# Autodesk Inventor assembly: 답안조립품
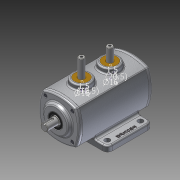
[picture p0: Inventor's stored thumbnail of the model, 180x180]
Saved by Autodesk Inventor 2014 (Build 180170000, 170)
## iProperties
Created: 2015-07
Part Number: 답안조립품
Document SubType Name: Assembly
Designer: Administrator
Mass: 2515.1 g
Surface Area: 1894.51 cm^2
Volume: 719.238 cm^3
Density: 3.4969 g/cm^3
Author: Administrator
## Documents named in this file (12)
- C:\Users\Administrator\Desktop\350727V1002\답안조립품.iam
- C:\Users\Administrator\Desktop\350727V1002\본체.ipt
- C:\Users\Administrator\Desktop\350727V1002\앞커버.ipt
- C:\Users\Administrator\Desktop\350727V1002\M4-소켓머리.ipt
- C:\Users\Administrator\Desktop\350727V1002\뒷커버.ipt
- C:\Users\Administrator\Desktop\350727V1002\오일실.ipt
- C:\Users\Administrator\Desktop\350727V1002\부시.ipt
- C:\Users\Administrator\Desktop\350727V1002\베어링 6203.ipt
- C:\Users\Administrator\Desktop\350727V1002\축.ipt
- C:\Users\Administrator\Desktop\350727V1002\슬라이더.ipt
- C:\Users\Administrator\Desktop\350727V1002\스프링.ipt
- C:\Users\Administrator\Desktop\350727V1002\스프링2.ipt
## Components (11 placed, 3 different names)
1. 8-오일실:1
2. 7-베어링 6203:1 — 각도:1
3. 7-베어링 6203:2 — 각도:2
4. 9-M4-소켓머리:1
5. 9-M4-소켓머리:2
6. 9-M4-소켓머리:3
7. 9-M4-소켓머리:4
8. 9-M4-소켓머리:5
9. 9-M4-소켓머리:6
10. 9-M4-소켓머리:7
11. 9-M4-소켓머리:8
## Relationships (2: Angle 2)
- 각도:1 [Angle]: 7-베어링 6203:1
- 각도:2 [Angle]: 7-베어링 6203:2
